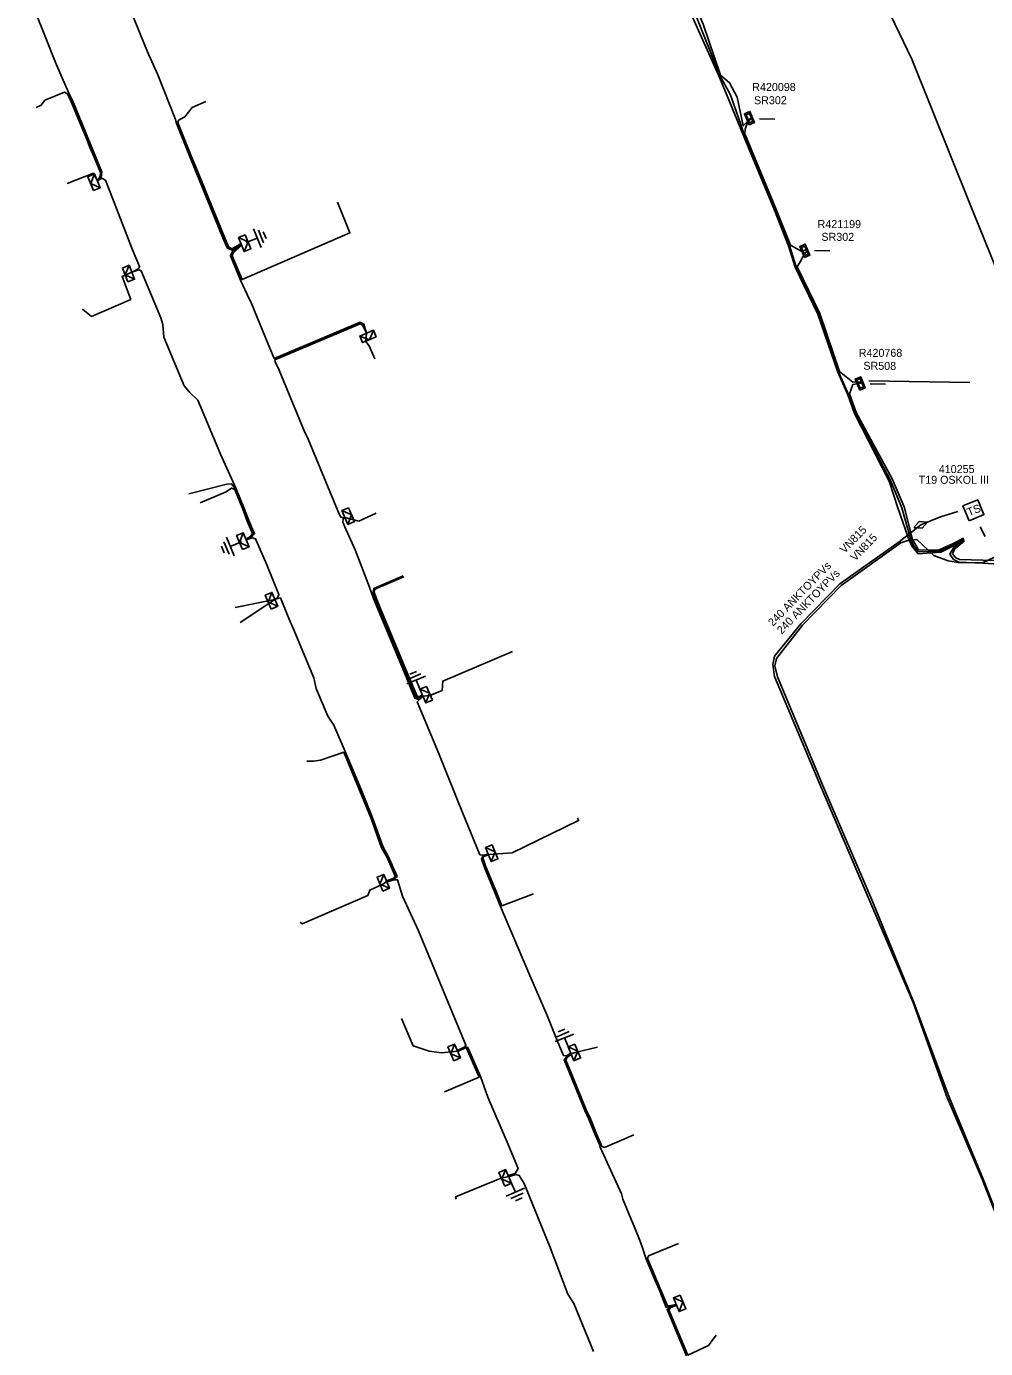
# Model space of a CAD drawing. Extents: x -540028 to -538776, y -1157064 to -1155670.
# Drawn here: x -539574.4 to -539454.6, y -1155979.1 to -1155813.9 of the extents above; entities that cross this region are included whole.
import ezdxf

# ---------------------------------------------------------------- set-up
doc = ezdxf.new("R2010")
doc.units = 0
for name, color, linetype in [('Vrstva 15', 7, 'Continuous'), ('Vrstva 19', 7, 'Continuous'), ('Vrstva 2', 7, 'Continuous'), ('Vrstva 25', 7, 'Continuous'), ('Vrstva 26', 7, 'Continuous'), ('Vrstva 27', 7, 'Continuous'), ('Vrstva 28', 7, 'Continuous'), ('Vrstva 29', 7, 'Continuous'), ('Vrstva 30', 7, 'Continuous'), ('Vrstva 31', 7, 'Continuous'), ('Vrstva 5', 7, 'Continuous'), ('Vrstva 52', 7, 'Continuous'), ('Vrstva 59', 7, 'Continuous'), ('Vrstva 6', 7, 'Continuous'), ('Vrstva 7', 7, 'Continuous')]:
    doc.layers.add(name, color=color, linetype=linetype)

# ---------------------------------------------------------------- blocks, each defined once
blk = doc.blocks.new('17')
at = {"layer": 'Vrstva 2'}
blk.add_lwpolyline([(-1.875, 0), (0, 0.9375), (1.875, 0), (0, -0.9375)], close=True, dxfattribs=at)
blk = doc.blocks.new('30')
at = {"layer": 'Vrstva 2'}
blk.add_lwpolyline([(-2, 0), (2, 0), (2, 4), (-2, 4)], close=True, dxfattribs=at)
blk.add_text('TS', height=2, dxfattribs=at).set_placement((-1.598, 1))
blk = doc.blocks.new('132')
at = {"layer": 'Vrstva 2'}
for points in [[(-1.5, 1.5), (1.5, 1.5), (1.5, 0), (-1.5, 0)], [(-1.1, 1.2), (1.1, 1.2), (1.1, 0.3), (-1.1, 0.3)]]:
    blk.add_lwpolyline(points, close=True, dxfattribs=at)
blk = doc.blocks.new('23')
at = {"layer": 'Vrstva 2'}
blk.add_lwpolyline([(1.875, -1.8), (-1.875, -1.8), (-1.875, 0), (1.875, 0)], close=True, dxfattribs=at)
blk.add_lwpolyline([(1.875, 0), (0, -1.8), (-1.875, 0)], dxfattribs=at)
blk = doc.blocks.new('11')
at = {"layer": 'Vrstva 2'}
for p, q in [((0, -4.3), (0, -1.3)), ((-2.5, -4.3), (2.5, -4.3)), ((-1.7, -5.3), (1.7, -5.3)), ((-0.9, -6.3), (0.9, -6.3))]:
    blk.add_line(p, q, dxfattribs=at)

msp = doc.modelspace()

# ---------------------------------------------------------------- linework, layer by layer
at = {"layer": 'Vrstva 5'}
for points in [[(-539450.64, -1155871.22), (-539448.38, -1155870.37), (-539445.91, -1155869.51), (-539445.16, -1155868.63), (-539444.2, -1155867.88), (-539444.08, -1155866.88), (-539445.32, -1155863.06), (-539447.87, -1155858.8), (-539451.16, -1155849.36), (-539456.5, -1155836.11), (-539463.8, -1155817.93), (-539469.08, -1155806.9), (-539474.9, -1155790.51), (-539482.11, -1155775.46), (-539488.3, -1155760.82), (-539493.72, -1155747.89), (-539499.46, -1155736.84), (-539501.89, -1155728.36)], [(-539494.98, -1155801.92), (-539494.9, -1155802.1), (-539494.9, -1155802.94), (-539494.17, -1155803.94), (-539487.8, -1155819.99), (-539486.51, -1155822.3), (-539485.16, -1155826.12), (-539484.76, -1155827.34), (-539480.87, -1155836.78), (-539479.08, -1155841.24), (-539478.26, -1155843.91), (-539475.43, -1155849.76), (-539472.96, -1155857.03), (-539471.7, -1155859.83), (-539470.88, -1155862.16), (-539466.46, -1155870.57), (-539465.04, -1155874), (-539463.95, -1155878.02), (-539463.54, -1155878.76), (-539463.03, -1155879.5), (-539460.34, -1155879.4), (-539458.72, -1155878.71), (-539457.35, -1155877.87)], [(-539483.78, -1155825.14), (-539484.86, -1155826.29), (-539485.63, -1155822.68), (-539486.57, -1155820.89), (-539487.69, -1155819.94), (-539489.88, -1155813.58), (-539491.73, -1155809.19), (-539490.82, -1155808.29)], [(-539574.42, -1155809.28), (-539572.35, -1155814.38), (-539571.1, -1155817.54), (-539570.65, -1155818.66), (-539569.12, -1155822.2), (-539568.64, -1155823.19), (-539566.74, -1155827.78), (-539565.77, -1155830.1), (-539564.98, -1155832.06), (-539565.07, -1155832.71), (-539565.56, -1155833.14), (-539565, -1155832.82), (-539564.55, -1155833.07), (-539564.25, -1155833.79), (-539561.17, -1155841.75), (-539560.29, -1155843.85), (-539560.41, -1155844.14), (-539561.25, -1155844.57)], [(-539531.92, -1155852.17), (-539532.28, -1155851.05), (-539532.72, -1155850.81), (-539543.47, -1155855.35), (-539544.2, -1155853.56), (-539546.32, -1155848.46), (-539546.84, -1155847.36), (-539547.66, -1155845.56), (-539548.93, -1155842.51), (-539548.68, -1155841.96), (-539547.57, -1155841.11), (-539547.63, -1155841.09), (-539548.73, -1155841.8), (-539549.35, -1155841.5), (-539549.87, -1155840.27), (-539553.98, -1155830.24), (-539555.73, -1155825.85), (-539555.8, -1155825.47), (-539558, -1155819.92), (-539559.28, -1155817.03), (-539562.16, -1155809.96)], [(-539457.28, -1155877.93), (-539458.68, -1155878.81), (-539460.18, -1155879.55), (-539463.01, -1155879.74), (-539463.72, -1155878.88), (-539464.1, -1155878.15), (-539465.51, -1155874.14), (-539466.65, -1155870.67), (-539470.99, -1155862.21), (-539471.81, -1155859.87), (-539473.07, -1155857.07), (-539475.55, -1155849.8), (-539478.37, -1155843.95), (-539479.2, -1155841.28), (-539480.98, -1155836.82), (-539484.87, -1155827.38), (-539486.94, -1155822.3), (-539487.91, -1155820.03), (-539492.98, -1155808.65)], [(-539483.73, -1155825.25), (-539484.28, -1155825.74), (-539484.63, -1155826.7), (-539484.65, -1155827.29), (-539480.76, -1155836.73), (-539478.97, -1155841.2), (-539477.53, -1155841.96), (-539476.88, -1155841.68)], [(-539476.83, -1155841.81), (-539477.4, -1155842.56), (-539477.76, -1155843.28), (-539478.14, -1155843.87), (-539475.32, -1155849.71), (-539472.84, -1155856.98), (-539471.19, -1155858.3), (-539469.97, -1155858.24)], [(-539561.25, -1155844.57), (-539560.37, -1155844.27), (-539560.08, -1155844.37), (-539557.62, -1155850.27), (-539557.38, -1155851.09), (-539557.25, -1155852.68), (-539554.7, -1155858.77), (-539554.03, -1155859.57), (-539552.99, -1155860.53), (-539550.19, -1155867.28), (-539548.22, -1155871.65), (-539547.22, -1155874.07), (-539546.65, -1155875.59), (-539545.92, -1155877.25), (-539546.31, -1155877.66), (-539546.97, -1155878), (-539546.23, -1155877.76), (-539545.79, -1155877.88), (-539544.39, -1155881.12), (-539542.87, -1155884.82), (-539543.05, -1155885.23), (-539543.32, -1155885.37), (-539543.39, -1155885.44), (-539543.3, -1155885.43), (-539543.03, -1155885.33), (-539542.68, -1155885.26), (-539541.7, -1155887.61), (-539540.94, -1155889.47), (-539538.53, -1155895.26), (-539538.21, -1155896.58), (-539536.76, -1155900.02), (-539536.03, -1155901.17), (-539534.59, -1155904.46), (-539532.62, -1155909.21), (-539531.17, -1155912.75), (-539529.86, -1155916.4), (-539529.21, -1155917.53), (-539528.11, -1155920.08), (-539528.45, -1155920.38), (-539529.42, -1155920.68), (-539529.21, -1155920.68), (-539528.47, -1155920.49), (-539528.05, -1155920.48), (-539527.44, -1155922.52), (-539525.42, -1155926.87), (-539519.52, -1155941.14), (-539519.67, -1155941.34), (-539520.5, -1155941.76), (-539520.57, -1155941.88), (-539519.52, -1155941.36), (-539519.29, -1155941.42), (-539517.69, -1155945.06), (-539516.78, -1155947.63), (-539514.35, -1155953.25), (-539512.99, -1155956.57), (-539513.35, -1155957.18), (-539514.09, -1155957.41), (-539514.19, -1155957.54), (-539514.06, -1155957.54), (-539513.29, -1155957.3), (-539512.85, -1155957.44), (-539512.22, -1155958.43), (-539511.07, -1155961.31), (-539509, -1155966.41), (-539506.77, -1155972.26), (-539506.03, -1155973.43), (-539503.56, -1155979.44)], [(-539491.97, -1155979.96), (-539494.39, -1155974.16), (-539493.95, -1155973.9), (-539493.3, -1155973.65), (-539493.23, -1155973.57), (-539494, -1155973.82), (-539494.48, -1155973.91), (-539495.38, -1155971.67), (-539495.87, -1155970.56), (-539496.99, -1155967.89), (-539497.5, -1155966.33), (-539497.93, -1155965.2), (-539499.93, -1155960.37), (-539500.08, -1155959.74), (-539502.73, -1155953.87), (-539502.84, -1155953.55), (-539503.32, -1155952.45), (-539504.18, -1155950.3), (-539504.66, -1155949.3), (-539506.28, -1155945.32), (-539507.24, -1155942.96), (-539506.91, -1155942.57), (-539506.38, -1155942.22), (-539506.48, -1155942.2), (-539506.95, -1155942.48), (-539507.33, -1155942.43), (-539507.59, -1155941.86), (-539508.05, -1155940.76), (-539509.37, -1155937.45), (-539511.8, -1155931.86), (-539515.2, -1155923.82), (-539515.89, -1155922.09), (-539517.19, -1155918.95), (-539517.57, -1155917.85), (-539517.37, -1155917.49), (-539516.7, -1155917.33), (-539516.79, -1155917.3), (-539517.39, -1155917.4), (-539517.77, -1155917.35), (-539520.42, -1155910.94), (-539522.93, -1155904.61), (-539525.59, -1155898.25), (-539524.95, -1155897.64), (-539524.9, -1155897.52), (-539525.45, -1155897.96), (-539525.88, -1155897.8), (-539526.98, -1155895.14), (-539528.86, -1155890.61), (-539530.66, -1155886.33), (-539531.06, -1155885.35), (-539531.3, -1155884.62), (-539531.55, -1155883.9), (-539533.35, -1155879.26), (-539534.52, -1155876.65), (-539534.88, -1155875.81), (-539534.85, -1155875.37), (-539534.64, -1155875.21), (-539534.88, -1155875.24), (-539535.2, -1155875.11), (-539535.53, -1155874.39), (-539539.23, -1155865.44), (-539539.71, -1155864.37), (-539542.85, -1155856.8), (-539543.35, -1155855.74), (-539543.39, -1155855.53), (-539532.73, -1155851.03), (-539532.44, -1155851.19), (-539531.92, -1155852.17)], [(-539457.35, -1155877.8), (-539458.79, -1155878.55), (-539460.38, -1155879.24), (-539462.97, -1155879.29), (-539463.31, -1155878.66), (-539463.71, -1155877.95), (-539464.75, -1155873.86), (-539466.27, -1155870.38), (-539470.77, -1155862.11), (-539471.59, -1155859.78), (-539471.18, -1155858.61), (-539469.92, -1155858.37)], [(-539462.7, -1155876.13), (-539460.22, -1155875.13), (-539458.07, -1155874.48)], [(-539462.7, -1155876.13), (-539465.39, -1155878.27), (-539472.81, -1155883.51), (-539477.68, -1155888.5), (-539480.97, -1155892.53), (-539481.18, -1155893.59), (-539480.97, -1155895.07), (-539475.09, -1155909.02), (-539463.64, -1155935.83), (-539459.38, -1155947.69), (-539455.04, -1155957.9), (-539448.51, -1155974.5)], [(-539451.04, -1155879), (-539454.99, -1155880.88), (-539458.03, -1155880.85), (-539459.27, -1155880.62), (-539461.07, -1155879.98), (-539463.18, -1155877.94), (-539464.32, -1155878.1), (-539465.19, -1155878.38), (-539472.65, -1155883.71), (-539477.48, -1155888.68), (-539480.71, -1155892.82), (-539480.91, -1155893.73), (-539480.58, -1155895.11), (-539474.86, -1155908.9), (-539468.67, -1155923.29), (-539463.55, -1155935.81), (-539459.14, -1155947.64), (-539454.88, -1155957.87), (-539448.36, -1155974.45)], [(-539457.28, -1155878), (-539458.59, -1155879.02), (-539459.04, -1155879.81), (-539458.59, -1155880.46), (-539457.95, -1155880.79), (-539454.95, -1155880.92), (-539443.5, -1155881.62)], [(-539457.21, -1155878.13), (-539458.42, -1155879.12), (-539458.73, -1155879.76), (-539458.33, -1155880.27), (-539457.84, -1155880.48), (-539454.92, -1155880.55), (-539444.05, -1155880.76)]]:
    msp.add_lwpolyline(points, dxfattribs=at)
at = {"layer": 'Vrstva 52'}
for points in [[(-539565.56, -1155833.14), (-539565.2, -1155832.58), (-539565.18, -1155832.1), (-539565.95, -1155830.18), (-539566.44, -1155829.05), (-539566.92, -1155827.86), (-539568.82, -1155823.27), (-539569.3, -1155822.28), (-539569.68, -1155822.07), (-539572.1, -1155823.05), (-539572.57, -1155823.71), (-539573.2, -1155824)], [(-539547.57, -1155841.11), (-539547.65, -1155841.01), (-539548.76, -1155841.66), (-539549.19, -1155841.38), (-539549.69, -1155840.19), (-539553.28, -1155831.3), (-539553.8, -1155830.16), (-539555.55, -1155825.77), (-539555.32, -1155825.52), (-539554.63, -1155825.15), (-539553.73, -1155823.98), (-539552, -1155823.25)], [(-539565.56, -1155833.14), (-539566.05, -1155832.18), (-539569.31, -1155833.47)], [(-539547.57, -1155841.11), (-539547.57, -1155841.2), (-539548.58, -1155842.19), (-539548.71, -1155842.51), (-539547.48, -1155845.48), (-539534.01, -1155839.63), (-539535.56, -1155835.83)], [(-539561.25, -1155844.57), (-539562.47, -1155845.1), (-539561.38, -1155847.97), (-539566.27, -1155850.09), (-539567.41, -1155849.2)], [(-539531.92, -1155852.17), (-539532.03, -1155853.21), (-539531.6, -1155853.75), (-539530.91, -1155855.38)], [(-539546.97, -1155878), (-539546.82, -1155877.86), (-539546.32, -1155877.6), (-539546.04, -1155877.23), (-539546.74, -1155875.63), (-539547.31, -1155874.11), (-539548.31, -1155871.69), (-539548.79, -1155871.01), (-539549.38, -1155871.03)], [(-539546.97, -1155878), (-539546.89, -1155877.84), (-539546.42, -1155877.58), (-539546.16, -1155877.21), (-539546.83, -1155875.67), (-539547.4, -1155874.15), (-539548.4, -1155871.73), (-539548.78, -1155871.53), (-539549.46, -1155872), (-539552.7, -1155873.38)], [(-539534.64, -1155875.21), (-539532.91, -1155875.66), (-539530.74, -1155874.66)], [(-539524.9, -1155897.52), (-539525.44, -1155897.8), (-539525.72, -1155897.66), (-539526.8, -1155895.06), (-539528.68, -1155890.53), (-539530.48, -1155886.25), (-539530.88, -1155885.29), (-539531.1, -1155884.56), (-539531.02, -1155884.07), (-539527.35, -1155882.5)], [(-539524.9, -1155897.52), (-539525.06, -1155897.45), (-539525.44, -1155897.64), (-539525.61, -1155897.55), (-539526.67, -1155895.01), (-539528.55, -1155890.48), (-539530.35, -1155886.2), (-539530.74, -1155885.24), (-539530.96, -1155884.55), (-539530.9, -1155884.17), (-539527.29, -1155882.63)], [(-539524.9, -1155897.52), (-539524.04, -1155897.47), (-539522.5, -1155896.81), (-539522.41, -1155895.65), (-539513.69, -1155891.96)], [(-539529.42, -1155920.68), (-539529.31, -1155920.57), (-539528.51, -1155920.29), (-539528.35, -1155920.03), (-539529.39, -1155917.61), (-539530.04, -1155916.48), (-539531.35, -1155912.83), (-539532.8, -1155909.29), (-539534.77, -1155904.54), (-539537.67, -1155905.52), (-539538.57, -1155905.64), (-539539.38, -1155905.64)], [(-539516.7, -1155917.33), (-539513.74, -1155917.11), (-539505.44, -1155913.08), (-539505.58, -1155912.76)], [(-539516.7, -1155917.33), (-539516.75, -1155917.4), (-539517.31, -1155917.58), (-539517.35, -1155917.85), (-539517.01, -1155918.88), (-539515.71, -1155922.01), (-539515.26, -1155923.12), (-539515.02, -1155923.74), (-539511.06, -1155922.24)], [(-539529.42, -1155920.68), (-539529.79, -1155920.99), (-539531.51, -1155921.76), (-539531.77, -1155922.46), (-539539.96, -1155925.99), (-539540.22, -1155925.77)], [(-539520.57, -1155941.88), (-539522.54, -1155942.12), (-539524.11, -1155941.88), (-539526.1, -1155941.21), (-539527.56, -1155937.82)], [(-539520.57, -1155941.88), (-539520.46, -1155941.89), (-539519.5, -1155941.44), (-539517.87, -1155945.14), (-539522.18, -1155946.96)], [(-539506.38, -1155942.22), (-539506.41, -1155942.31), (-539506.85, -1155942.67), (-539507.02, -1155943), (-539506.1, -1155945.24), (-539504.48, -1155949.22), (-539504, -1155950.22), (-539503.14, -1155952.37), (-539502.66, -1155953.47), (-539502.55, -1155953.81), (-539502.19, -1155953.93), (-539498.54, -1155952.36)], [(-539506.38, -1155942.22), (-539505.87, -1155942.08), (-539503.09, -1155941.39)], [(-539514.19, -1155957.54), (-539515.23, -1155957.79), (-539520.83, -1155960.11), (-539520.73, -1155960.37)], [(-539493.23, -1155973.57), (-539493.32, -1155973.53), (-539494.02, -1155973.7), (-539494.34, -1155973.71), (-539495.69, -1155970.48), (-539496.81, -1155967.81), (-539496.69, -1155967.46), (-539492.96, -1155965.91)], [(-539493.23, -1155973.57), (-539493.26, -1155973.67), (-539493.92, -1155973.94), (-539494.15, -1155974.2), (-539491.79, -1155979.88), (-539489.21, -1155978.67), (-539488.26, -1155977.4)]]:
    msp.add_lwpolyline(points, dxfattribs=at)
at = {"layer": 'Vrstva 59'}
for points in [[(-539482.82, -1155825.38), (-539480.91, -1155825.43)], [(-539475.97, -1155841.85), (-539474.05, -1155841.9)], [(-539469.16, -1155858.14), (-539456.56, -1155858.34)], [(-539469.01, -1155858.53), (-539467.09, -1155858.57)], [(-539549.38, -1155871.03), (-539554.11, -1155872.26)], [(-539455.26, -1155876.37), (-539454.64, -1155877.6)], [(-539543.39, -1155885.44), (-539548.33, -1155886.46)], [(-539543.39, -1155885.44), (-539547.71, -1155888.34)]]:
    msp.add_lwpolyline(points, dxfattribs=at)

# ---------------------------------------------------------------- block references
at = {"layer": 'Vrstva 15'}
for p, xscale, yscale, rotation in [((-539547.57, -1155841.11), 0.5000000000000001, 0.4999999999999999, 112.2198555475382), ((-539546.97, -1155878), 0.5, 0.5, -67.35741105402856), ((-539524.9, -1155897.52), 0.5, 0.5, -157.42166109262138), ((-539506.38, -1155942.22), 0.5, 0.5000000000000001, -157.62782506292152), ((-539514.19, -1155957.54), 0.5, 0.49999999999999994, 23.79718049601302)]:
    msp.add_blockref('11', p, dxfattribs=dict(at, xscale=xscale, yscale=yscale, rotation=rotation))
at = {"layer": 'Vrstva 19', "xscale": 0.5, "yscale": 0.5, "rotation": 21.960563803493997}
msp.add_blockref('17', (-539462.7, -1155876.13), dxfattribs=at)
at = {"layer": 'Vrstva 25', "xscale": 0.5, "yscale": 0.5, "rotation": 22.569369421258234}
msp.add_blockref('30', (-539455.73, -1155875.23), dxfattribs=at)
at = {"layer": 'Vrstva 28'}
for p, xscale, yscale, rotation in [((-539483.74, -1155825.16), 0.5000000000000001, 0.4999999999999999, 112.72559998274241), ((-539476.83, -1155841.74), 0.5000000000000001, 0.5, 112.62121396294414), ((-539469.91, -1155858.31), 0.5, 0.5, 112.62201665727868)]:
    msp.add_blockref('132', p, dxfattribs=dict(at, xscale=xscale, yscale=yscale, rotation=rotation))
at = {"layer": 'Vrstva 31'}
for p, xscale, yscale, rotation in [((-539565.56, -1155833.14), 0.5, 0.5, -67.16634439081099), ((-539547.56, -1155841.11), 0.5000000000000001, 0.4999999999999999, 112.2198555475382), ((-539561.25, -1155844.57), 0.5, 0.5, -67.98638614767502), ((-539531.92, -1155852.17), 0.5, 0.5, 22.900449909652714), ((-539534.64, -1155875.21), 0.5, 0.5000000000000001, 112.88042772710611), ((-539546.97, -1155878), 0.5000000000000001, 0.5, -67.35741111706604), ((-539543.39, -1155885.44), 0.49999999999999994, 0.5000000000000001, -66.80140834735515), ((-539524.9, -1155897.52), 0.5, 0.5, 112.57833884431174), ((-539516.7, -1155917.33), 0.5, 0.5000000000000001, 112.26356663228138), ((-539529.42, -1155920.68), 0.5000000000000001, 0.4999999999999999, -67.51365266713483), ((-539520.57, -1155941.88), 0.5000000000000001, 0.5, -67.42485558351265), ((-539506.38, -1155942.22), 0.5, 0.5, 112.37217503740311), ((-539514.19, -1155957.54), 0.5, 0.5, -66.20281944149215), ((-539493.23, -1155973.57), 0.49999999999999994, 0.5, 112.05841940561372)]:
    msp.add_blockref('23', p, dxfattribs=dict(at, xscale=xscale, yscale=yscale, rotation=rotation))

# ---------------------------------------------------------------- texts
at = {"layer": 'Vrstva 26'}
msp.add_text('410255', height=1, dxfattribs=at).set_placement((-539460.44, -1155869.66))
at = {"layer": 'Vrstva 27'}
msp.add_text('T19 OSKOL III', height=1, dxfattribs=at).set_placement((-539462.95, -1155871))
at = {"layer": 'Vrstva 29'}
for s, p in [('R420098', (-539483.74, -1155821.92)), ('R421199', (-539475.58, -1155839.05)), ('R420768', (-539470.43, -1155855.14))]:
    msp.add_text(s, height=1, dxfattribs=at).set_placement(p)
at = {"layer": 'Vrstva 30'}
for s, rotation, p in [('SR302', 0.192, (-539483.52, -1155823.58)), ('SR302', 359.94, (-539475.1, -1155840.64)), ('SR508', 359.645, (-539469.86, -1155856.75))]:
    msp.add_text(s, height=1, rotation=rotation, dxfattribs=at).set_placement(p)
at = {"layer": 'Vrstva 6'}
for rotation, p in [(45.715, (-539481.16, -1155888.88)), (45.83, (-539480.06, -1155889.85))]:
    msp.add_text('240 ANKTOYPVs', height=1, rotation=rotation, dxfattribs=at).set_placement(p)
at = {"layer": 'Vrstva 7'}
for rotation, p in [(45.715, (-539472.21, -1155879.77)), (45.83, (-539470.88, -1155880.74))]:
    msp.add_text('VN815', height=1, rotation=rotation, dxfattribs=at).set_placement(p)

doc.saveas('drawing.dxf')
